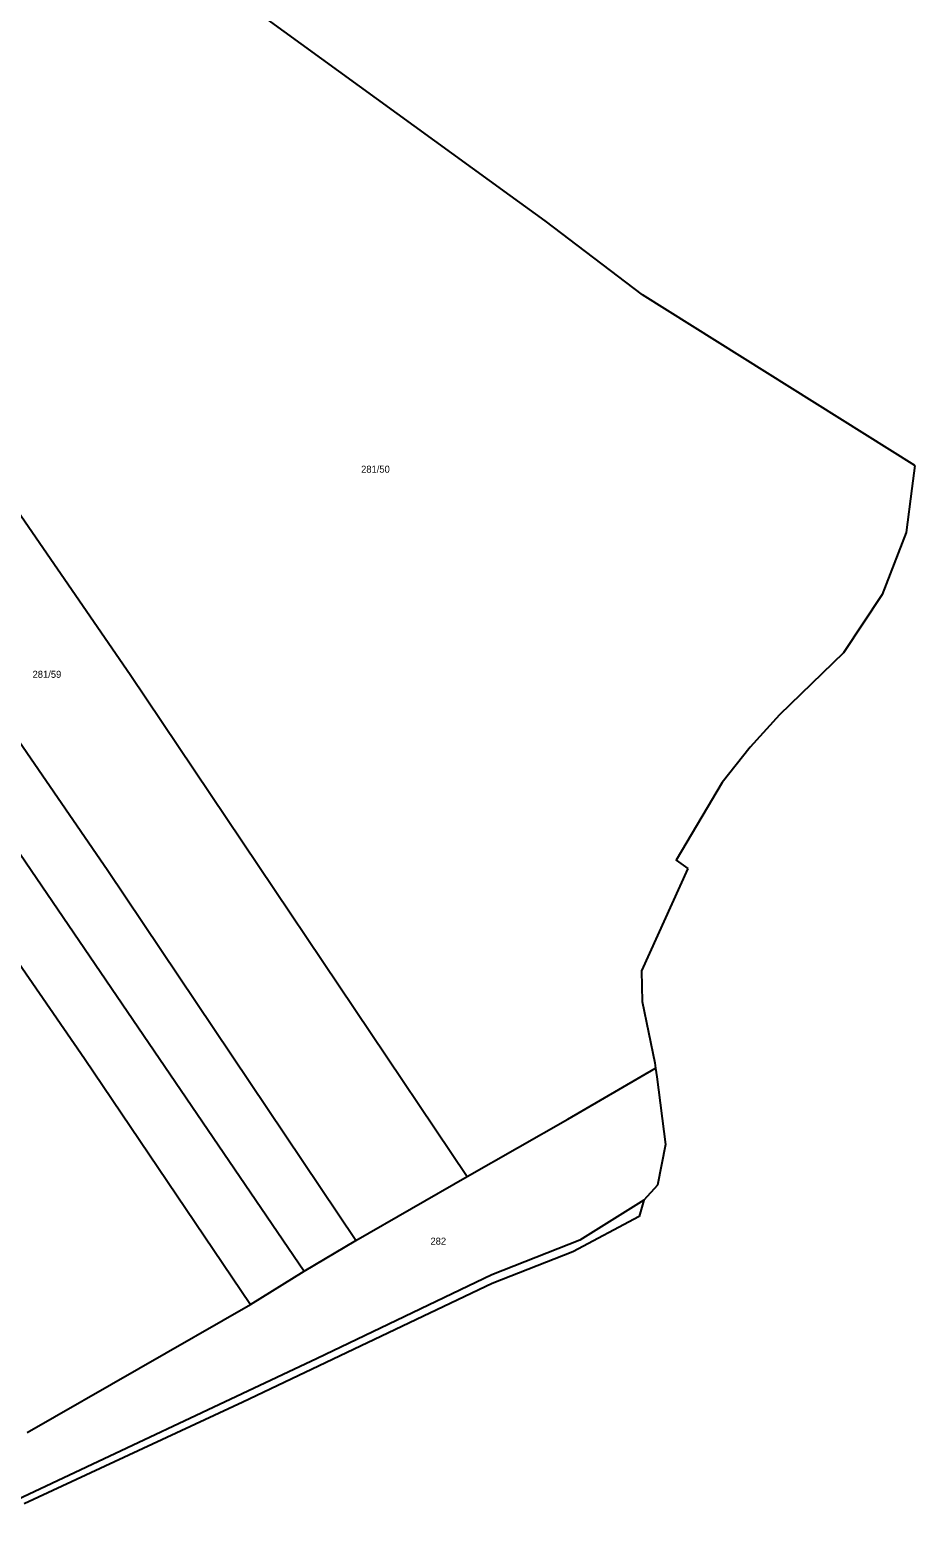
# Model space of a CAD drawing. Extents: x -779723 to -777378, y -1011169 to -1009297.
# Drawn here: x -777592.6 to -777378.3, y -1010788.9 to -1010423.7 of the extents above; entities that cross this region are included whole.
import ezdxf

# ---------------------------------------------------------------- set-up
doc = ezdxf.new("R2010")
doc.units = 0
doc.layers.add('Hranice parcel', color=7, linetype='Continuous')
doc.layers.add('Parcelní čísla', color=7, linetype='Continuous')

msp = doc.modelspace()

# ---------------------------------------------------------------- linework, layer by layer
at = {"layer": 'Hranice parcel'}
for p, q in [((-777467.85, -1010469.89), (-777476.3, -1010463.75)), ((-777444.27, -1010487.85), (-777467.85, -1010469.89)), ((-777378.31, -1010529.19), (-777444.27, -1010487.85)), ((-777433.29, -1010626.8), (-777444.54, -1010651.54)), ((-777513.72, -1010716.86), (-777486.74, -1010701.34)), ((-777443.92, -1010707.06), (-777445.06, -1010711.01)), ((-777526.23, -1010724.31), (-777513.72, -1010716.86)), ((-777539.17, -1010732.39), (-777526.23, -1010724.31)), ((-777593.25, -1010763.39), (-777539.17, -1010732.39))]:
    msp.add_line(p, q, dxfattribs=at)
for points in [[(-777476.3, -1010463.75), (-777554.28, -1010407.13), (-777588.84, -1010382.03)], [(-777673.1, -1010427.53), (-777568.32, -1010579.76), (-777486.74, -1010701.34)], [(-777513.72, -1010716.86), (-777573.74, -1010627.31), (-777637.27, -1010534.93), (-777701.02, -1010442.3)], [(-777714.87, -1010450.31), (-777601.48, -1010613.75), (-777526.23, -1010724.31)], [(-777728.3, -1010456.89), (-777653.97, -1010564.65), (-777579.37, -1010672.78), (-777539.17, -1010732.39)], [(-777378.31, -1010529.19), (-777379.04, -1010534.71), (-777380.45, -1010545.4), (-777386.25, -1010560.41), (-777395.6, -1010574.52), (-777411.07, -1010589.55), (-777418.22, -1010597.38), (-777425.01, -1010605.94), (-777436.13, -1010624.72), (-777433.29, -1010626.8)], [(-777444.54, -1010651.54), (-777444.36, -1010658.99), (-777441.24, -1010673.81), (-777441.08, -1010675.09)], [(-777486.74, -1010701.34), (-777462.35, -1010687.47), (-777441.08, -1010675.09)], [(-777441.08, -1010675.09), (-777440.81, -1010677.2), (-777438.71, -1010693.65), (-777440.66, -1010703.46), (-777443.92, -1010707.06)], [(-777443.92, -1010707.06), (-777459.4, -1010716.74), (-777480.75, -1010725.19), (-777523.08, -1010745.44), (-777597.11, -1010780.27), (-777621.57, -1010788.87)], [(-777445.06, -1010711.01), (-777461.16, -1010719.58), (-777480.67, -1010727.25)], [(-777480.67, -1010727.25), (-777541.04, -1010756.05), (-777593.97, -1010780.61)]]:
    msp.add_lwpolyline(points, dxfattribs=at)

# ---------------------------------------------------------------- texts
at = {"layer": 'Parcelní čísla'}
for s, p in [('281/50', (-777512.41, -1010530.92)), ('281/59', (-777591.97, -1010580.59)), ('282', (-777495.61, -1010717.86))]:
    msp.add_text(s, height=1.7, dxfattribs=at).set_placement(p)

doc.saveas('drawing.dxf')
